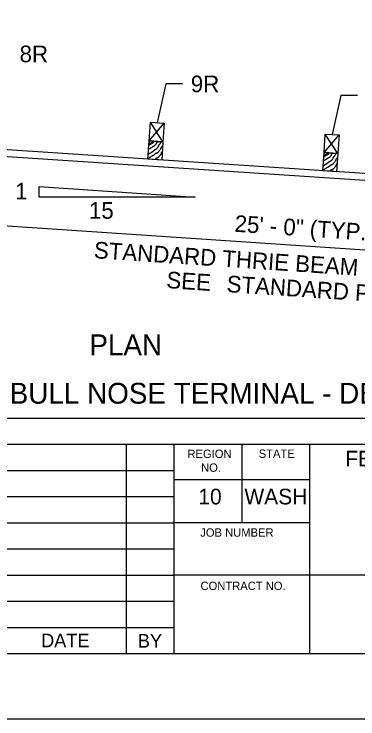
# Model space of a CAD drawing. Extents: x 1312564.2 to 1312581.5, y 1207298.4 to 1207352.6.
# Drawn here: x 1312570.095 to 1312571.742, y 1207298.421 to 1207301.791 of the extents above; entities that cross this region are included whole.
import ezdxf

# ---------------------------------------------------------------- set-up
doc = ezdxf.new("R2010")
doc.units = 0
for name, color, linetype in [('Level 1', 7, 'Continuous'), ('Level 13', 7, 'Continuous'), ('Level 14', 7, 'Continuous'), ('Level 15', 7, 'Continuous'), ('Level 2', 7, 'Continuous'), ('Level 20', 7, 'Continuous'), ('SH_GI_SheetTextInCells', 7, 'Continuous')]:
    doc.layers.add(name, color=color, linetype=linetype)

msp = doc.modelspace()

# ---------------------------------------------------------------- linework, layer by layer
at = {"layer": 'Level 1'}
for p, q in [((1312565.4154872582, 1207299.8593171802), (1312581.1654872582, 1207299.8593171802)), ((1312565.4154872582, 1207299.7342171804), (1312572.8721328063, 1207299.7342171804)), ((1312570.6319170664, 1207299.7342171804), (1312570.6319170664, 1207298.7334171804)), ((1312570.8605498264, 1207299.7342171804), (1312570.8605498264, 1207298.7334171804)), ((1312571.1873610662, 1207299.3589171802), (1312571.1873610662, 1207299.7342171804)), ((1312571.5110448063, 1207298.7334171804), (1312571.5110448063, 1207299.7342171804)), ((1312567.5976316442, 1207299.60911418), (1312570.8621007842, 1207299.60911418)), ((1312571.5112449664, 1207299.5644114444), (1312570.8621010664, 1207299.5644114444)), ((1312567.5976316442, 1207299.48401418), (1312570.8621007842, 1207299.48401418)), ((1312565.4154872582, 1207299.3589171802), (1312570.8621010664, 1207299.3589171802)), ((1312571.5112449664, 1207299.3589171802), (1312570.8621010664, 1207299.3589171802)), ((1312565.4154872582, 1207299.2338171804), (1312570.8621010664, 1207299.2338171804)), ((1312565.4154872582, 1207299.1087171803), (1312570.8621010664, 1207299.1087171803)), ((1312572.8721328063, 1207299.1087171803), (1312570.8621010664, 1207299.1087171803)), ((1312565.4154872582, 1207298.9836171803), (1312570.8621010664, 1207298.9836171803)), ((1312565.4154872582, 1207298.8585171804), (1312570.8621010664, 1207298.8585171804)), ((1312565.4154872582, 1207298.7334171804), (1312581.1654872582, 1207298.7334171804))]:
    msp.add_line(p, q, dxfattribs=at)
at = {"layer": 'Level 13'}
for points in [[(1312570.8071573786, 1207301.163427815), (1312570.8027456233, 1207301.1569541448), (1312570.802085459, 1207301.1562888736), (1312570.8012732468, 1207301.155764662), (1312570.8004554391, 1207301.1552460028), (1312570.7997784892, 1207301.1545973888), (1312570.7992182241, 1207301.1536536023), (1312570.7988187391, 1207301.152627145), (1312570.7983023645, 1207301.1504244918), (1312570.7978298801, 1207301.1481859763), (1312570.797264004, 1207301.1466017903), (1312570.7970017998, 1207301.1461081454), (1312570.793941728, 1207301.141220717), (1312570.7905743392, 1207301.1365573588), (1312570.7868166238, 1207301.1321866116), (1312570.784765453, 1207301.130132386), (1312570.7836922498, 1207301.1291418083), (1312570.7825855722, 1207301.1281770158), (1312570.7811749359, 1207301.12716844), (1312570.779645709, 1207301.1263642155), (1312570.776395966, 1207301.1251071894), (1312570.7731653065, 1207301.1238826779), (1312570.7709527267, 1207301.1226708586), (1312570.7702826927, 1207301.1221674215), (1312570.7695642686, 1207301.1214058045), (1312570.7689385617, 1207301.1205293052), (1312570.7682930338, 1207301.1196731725), (1312570.767515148, 1207301.1189726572), (1312570.763791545, 1207301.1166892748), (1312570.7599829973, 1207301.1145276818), (1312570.7561839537, 1207301.1123467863), (1312570.7524888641, 1207301.1100054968), (1312570.7368510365, 1207301.0993171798)], [(1312570.8003638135, 1207301.1814220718), (1312570.7972739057, 1207301.1764844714), (1312570.7954083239, 1207301.173580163), (1312570.793484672, 1207301.170712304), (1312570.7915210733, 1207301.167873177), (1312570.789535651, 1207301.1650550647), (1312570.7892304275, 1207301.1647300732), (1312570.7888550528, 1207301.1644801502), (1312570.7879852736, 1207301.1641077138), (1312570.7871091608, 1207301.163742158), (1312570.7864095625, 1207301.1631878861), (1312570.7860680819, 1207301.1626926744), (1312570.7857782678, 1207301.16216852), (1312570.7853252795, 1207301.161048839), (1312570.7847273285, 1207301.1586321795), (1312570.7841619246, 1207301.1561852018), (1312570.78348625, 1207301.1544788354), (1312570.7831752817, 1207301.1539552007), (1312570.7814320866, 1207301.1514727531), (1312570.7795401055, 1207301.1490977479), (1312570.777487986, 1207301.1468514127), (1312570.775264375, 1207301.144754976), (1312570.7741153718, 1207301.1439121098), (1312570.7728579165, 1207301.143232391), (1312570.7701697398, 1207301.1421474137), (1312570.767504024, 1207301.1410700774), (1312570.766274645, 1207301.1403999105), (1312570.7651649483, 1207301.139570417), (1312570.764742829, 1207301.1389820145), (1312570.7644500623, 1207301.138271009), (1312570.7641374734, 1207301.137580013), (1312570.763655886, 1207301.137051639), (1312570.7376506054, 1207301.1201799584)], [(1312570.783531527, 1207301.182544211), (1312570.7791813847, 1207301.1762695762), (1312570.7789475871, 1207301.1760503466), (1312570.7786440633, 1207301.175924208), (1312570.777919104, 1207301.1758288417), (1312570.7771890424, 1207301.175738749), (1312570.7766364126, 1207301.1754092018), (1312570.7764793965, 1207301.1751753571), (1312570.7763493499, 1207301.1749273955), (1312570.7761555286, 1207301.1743966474), (1312570.7759305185, 1207301.1732485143), (1312570.7757272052, 1207301.1720851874), (1312570.775560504, 1207301.1715354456), (1312570.77531141, 1207301.1710270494), (1312570.774418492, 1207301.1696106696), (1312570.7734979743, 1207301.1682062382), (1312570.771536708, 1207301.1654696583), (1312570.7681538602, 1207301.161682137), (1312570.7675235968, 1207301.1611025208), (1312570.7668712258, 1207301.1605406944), (1312570.765961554, 1207301.1599116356), (1312570.7649721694, 1207301.1594263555), (1312570.7628654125, 1207301.1587027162), (1312570.7607732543, 1207301.1580009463), (1312570.7593474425, 1207301.1572670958), (1312570.7591293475, 1207301.1571148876), (1312570.7589179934, 1207301.1569522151), (1312570.758344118, 1207301.1563314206), (1312570.7578531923, 1207301.1556066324), (1312570.757340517, 1207301.1549060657), (1312570.756701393, 1207301.1543579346), (1312570.7409179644, 1207301.145169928)], [(1312570.7667394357, 1207301.1836636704), (1312570.7651913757, 1207301.1814273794), (1312570.7648477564, 1207301.18091515), (1312570.7645125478, 1207301.18038888), (1312570.7625128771, 1207301.1771599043), (1312570.7609746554, 1207301.1752319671), (1312570.7590522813, 1207301.1737817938), (1312570.7526782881, 1207301.1704850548), (1312570.7420683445, 1207301.1649974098)], [(1312570.7587838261, 1207301.184194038), (1312570.7584000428, 1207301.1824398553), (1312570.757974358, 1207301.1807241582), (1312570.7573869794, 1207301.1791569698), (1312570.7569952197, 1207301.1784634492), (1312570.7567682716, 1207301.1781452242), (1312570.7566462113, 1207301.1779939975), (1312570.7565829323, 1207301.1779204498), (1312570.756550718, 1207301.177884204), (1312570.7565344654, 1207301.177866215), (1312570.756518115, 1207301.177848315), (1312570.7562144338, 1207301.1775351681), (1312570.755893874, 1207301.1772375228), (1312570.7552054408, 1207301.1766856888), (1312570.7536625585, 1207301.1757344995), (1312570.7500986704, 1207301.174271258), (1312570.7462514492, 1207301.173068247), (1312570.7443544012, 1207301.1724423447), (1312570.7425458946, 1207301.171735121)], [(1312570.8052260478, 1207301.1344575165), (1312570.8045071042, 1207301.1334083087), (1312570.804205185, 1207301.1330493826), (1312570.8038470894, 1207301.1327426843), (1312570.803035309, 1207301.1322182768), (1312570.802217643, 1207301.1316996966), (1312570.8018521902, 1207301.1314002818), (1312570.8015399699, 1207301.1310515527), (1312570.8009784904, 1207301.130108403), (1312570.8005784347, 1207301.1290822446), (1312570.800062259, 1207301.1268794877), (1312570.7995907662, 1207301.1246404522), (1312570.799246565, 1207301.1235689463), (1312570.7987632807, 1207301.1225623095), (1312570.7980218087, 1207301.1213237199), (1312570.7972637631, 1207301.1200968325), (1312570.7923110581, 1207301.113029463), (1312570.7885502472, 1207301.1086609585), (1312570.7865079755, 1207301.1066002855), (1312570.7854428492, 1207301.1056038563), (1312570.7843470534, 1207301.1046311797), (1312570.7829254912, 1207301.1036415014), (1312570.781347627, 1207301.1028991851), (1312570.7779691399, 1207301.1017981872), (1312570.7747038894, 1207301.1006112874), (1312570.773267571, 1207301.099761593), (1312570.772044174, 1207301.0986215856), (1312570.770850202, 1207301.0971178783)], [(1312571.6443803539, 1207301.1076136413), (1312571.6399685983, 1207301.1011399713), (1312571.6393084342, 1207301.1004746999), (1312571.638496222, 1207301.0999504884), (1312571.6376784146, 1207301.0994318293), (1312571.6370014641, 1207301.098783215), (1312571.636441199, 1207301.0978394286), (1312571.636041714, 1207301.0968129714), (1312571.6355253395, 1207301.094610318), (1312571.6350528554, 1207301.0923718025), (1312571.634486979, 1207301.0907876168), (1312571.6342247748, 1207301.0902939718), (1312571.631164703, 1207301.0854065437), (1312571.6277973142, 1207301.0807431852), (1312571.6240395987, 1207301.0763724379), (1312571.621988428, 1207301.0743182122), (1312571.620915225, 1207301.0733276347), (1312571.6198085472, 1207301.072362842), (1312571.6183979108, 1207301.0713542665), (1312571.616868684, 1207301.070550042), (1312571.613618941, 1207301.0692930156), (1312571.6103882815, 1207301.0680685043), (1312571.6081757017, 1207301.066856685), (1312571.6075056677, 1207301.0663532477), (1312571.606787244, 1207301.0655916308), (1312571.6061615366, 1207301.0647151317), (1312571.6055160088, 1207301.0638589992), (1312571.6047381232, 1207301.0631584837), (1312571.60101452, 1207301.0608751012), (1312571.5972059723, 1207301.058713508), (1312571.5934069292, 1207301.0565326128), (1312571.589711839, 1207301.0541913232), (1312571.5740740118, 1207301.0435030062)], [(1312571.6375867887, 1207301.1256078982), (1312571.6344968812, 1207301.1206702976), (1312571.6326312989, 1207301.1177659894), (1312571.630707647, 1207301.1148981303), (1312571.6287440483, 1207301.1120590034), (1312571.626758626, 1207301.1092408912), (1312571.6264534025, 1207301.1089158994), (1312571.6260780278, 1207301.108665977), (1312571.6252082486, 1207301.1082935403), (1312571.624332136, 1207301.1079279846), (1312571.6236325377, 1207301.1073737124), (1312571.6232910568, 1207301.106878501), (1312571.623001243, 1207301.1063543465), (1312571.6225482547, 1207301.1052346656), (1312571.6219503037, 1207301.1028180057), (1312571.6213848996, 1207301.1003710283), (1312571.620709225, 1207301.0986646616), (1312571.6203982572, 1207301.098141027), (1312571.6186550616, 1207301.0956585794), (1312571.6167630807, 1207301.093283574), (1312571.614710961, 1207301.0910372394), (1312571.61248735, 1207301.0889408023), (1312571.6113383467, 1207301.088097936), (1312571.6100808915, 1207301.0874182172), (1312571.6073927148, 1207301.08633324), (1312571.6047269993, 1207301.0852559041), (1312571.60349762, 1207301.084585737), (1312571.6023879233, 1207301.0837562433), (1312571.601965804, 1207301.083167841), (1312571.6016730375, 1207301.0824568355), (1312571.6013604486, 1207301.0817658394), (1312571.6008788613, 1207301.0812374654), (1312571.5748735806, 1207301.0643657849)], [(1312571.620754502, 1207301.1267300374), (1312571.6164043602, 1207301.1204554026), (1312571.6161705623, 1207301.1202361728), (1312571.6158670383, 1207301.1201100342), (1312571.6151420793, 1207301.1200146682), (1312571.6144120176, 1207301.1199245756), (1312571.6138593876, 1207301.119595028), (1312571.6137023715, 1207301.1193611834), (1312571.6135723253, 1207301.119113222), (1312571.6133785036, 1207301.1185824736), (1312571.6131534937, 1207301.1174343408), (1312571.6129501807, 1207301.1162710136), (1312571.6127834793, 1207301.115721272), (1312571.6125343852, 1207301.1152128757), (1312571.6116414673, 1207301.113796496), (1312571.6107209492, 1207301.1123920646), (1312571.6087596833, 1207301.1096554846), (1312571.605376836, 1207301.1058679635), (1312571.6047465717, 1207301.105288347), (1312571.6040942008, 1207301.1047265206), (1312571.6031845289, 1207301.104097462), (1312571.6021951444, 1207301.103612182), (1312571.6000883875, 1207301.102888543), (1312571.5979962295, 1207301.1021867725), (1312571.5965704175, 1207301.1014529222), (1312571.5963523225, 1207301.1013007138), (1312571.5961409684, 1207301.1011380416), (1312571.5955670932, 1207301.1005172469), (1312571.5950761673, 1207301.0997924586), (1312571.5945634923, 1207301.099091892), (1312571.593924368, 1207301.098543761), (1312571.5781409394, 1207301.0893557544)], [(1312571.6039624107, 1207301.1278494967), (1312571.6024143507, 1207301.125613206), (1312571.6020707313, 1207301.1251009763), (1312571.6017355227, 1207301.1245747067), (1312571.599735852, 1207301.1213457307), (1312571.5981976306, 1207301.1194177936), (1312571.5962752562, 1207301.11796762), (1312571.5899012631, 1207301.1146708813), (1312571.5792913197, 1207301.1091832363)], [(1312571.5960068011, 1207301.1283798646), (1312571.5956230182, 1207301.1266256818), (1312571.595197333, 1207301.1249099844), (1312571.5946099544, 1207301.1233427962), (1312571.5942181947, 1207301.122649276), (1312571.5939912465, 1207301.1223310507), (1312571.5938691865, 1207301.1221798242), (1312571.5938059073, 1207301.1221062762), (1312571.593773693, 1207301.1220700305), (1312571.5937574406, 1207301.122052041), (1312571.5937410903, 1207301.1220341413), (1312571.593437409, 1207301.1217209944), (1312571.5931168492, 1207301.121423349), (1312571.5924284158, 1207301.1208715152), (1312571.5908855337, 1207301.119920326), (1312571.5873216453, 1207301.1184570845), (1312571.5834744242, 1207301.1172540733), (1312571.5815773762, 1207301.1166281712), (1312571.5797688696, 1207301.1159209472)], [(1312571.642449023, 1207301.0786433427), (1312571.6417300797, 1207301.0775941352), (1312571.64142816, 1207301.0772352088), (1312571.6410700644, 1207301.0769285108), (1312571.640258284, 1207301.0764041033), (1312571.6394406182, 1207301.0758855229), (1312571.6390751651, 1207301.0755861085), (1312571.638762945, 1207301.0752373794), (1312571.6382014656, 1207301.0742942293), (1312571.6378014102, 1207301.073268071), (1312571.6372852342, 1207301.0710653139), (1312571.6368137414, 1207301.0688262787), (1312571.63646954, 1207301.0677547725), (1312571.6359862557, 1207301.0667481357), (1312571.6352447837, 1207301.065509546), (1312571.6344867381, 1207301.0642826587), (1312571.6295340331, 1207301.0572152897), (1312571.6257732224, 1207301.052846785), (1312571.6237309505, 1207301.0507861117), (1312571.6226658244, 1207301.0497896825), (1312571.6215700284, 1207301.0488170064), (1312571.6201484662, 1207301.0478273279), (1312571.618570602, 1207301.0470850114), (1312571.6151921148, 1207301.0459840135), (1312571.6119268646, 1207301.0447971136), (1312571.6104905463, 1207301.0439474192), (1312571.609267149, 1207301.042807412), (1312571.608073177, 1207301.0413037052)]]:
    msp.add_spline(points, degree=3, dxfattribs=at)
at = {"layer": 'Level 14'}
for p, q in [((1312570.7421442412, 1207301.1853033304), (1312570.8142069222, 1207301.269172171)), ((1312570.8083216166, 1207301.1808915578), (1312570.748029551, 1207301.273583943)), ((1312571.5793672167, 1207301.1294891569), (1312571.6514298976, 1207301.2133579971)), ((1312571.6455445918, 1207301.1250773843), (1312571.5852525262, 1207301.2177697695))]:
    msp.add_line(p, q, dxfattribs=at)
at = {"layer": 'Level 15'}
for p, q in [((1312570.821919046, 1207301.4573174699), (1312570.7811182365, 1207301.2713780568)), ((1312570.9016476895, 1207301.4573174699), (1312570.821919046, 1207301.4573174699)), ((1312571.6591420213, 1207301.401503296), (1312571.6183412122, 1207301.2155638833)), ((1312571.7388706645, 1207301.401503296), (1312571.6591420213, 1207301.401503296)), ((1312568.209466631, 1207301.2673344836), (1312575.5205605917, 1207300.7799342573)), ((1312568.207260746, 1207301.234245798), (1312575.5205605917, 1207300.7466985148)), ((1312570.2153975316, 1207300.9162212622), (1312570.2153975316, 1207300.9660516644)), ((1312570.2153975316, 1207300.9660516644), (1312570.9628535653, 1207300.9162212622)), ((1312570.9628535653, 1207300.9162212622), (1312570.2153975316, 1207300.9162212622)), ((1312569.9194786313, 1207300.7877419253), (1312573.229335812, 1207300.5670875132))]:
    msp.add_line(p, q, dxfattribs=at)
for points in [[(1312570.8083216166, 1207301.1808915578), (1312570.7421442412, 1207301.1853033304), (1312570.748029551, 1207301.273583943), (1312570.8142069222, 1207301.269172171)], [(1312571.6455445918, 1207301.1250773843), (1312571.5793672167, 1207301.1294891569), (1312571.5852525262, 1207301.2177697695), (1312571.6514298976, 1207301.2133579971)], [(1312570.8024363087, 1207301.0926109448), (1312570.7362589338, 1207301.0970227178), (1312570.7421442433, 1207301.1853033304), (1312570.8083216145, 1207301.180891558)], [(1312571.6396592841, 1207301.0367967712), (1312571.5734819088, 1207301.041208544), (1312571.5793672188, 1207301.1294891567), (1312571.6455445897, 1207301.1250773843)]]:
    msp.add_lwpolyline(points, close=True, dxfattribs=at)
at = {"layer": 'Level 2'}
msp.add_lwpolyline([(1312564.4779872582, 1207298.4209171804), (1312581.4779872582, 1207298.4209171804), (1312581.4779872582, 1207309.4209171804), (1312564.4779872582, 1207309.4209171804)], close=True, dxfattribs=at)

# ---------------------------------------------------------------- texts
at = {"layer": 'Level 20'}
for s, height, p in [('8R', 0.07972865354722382, (1312570.1219565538, 1207301.5607624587)), ('9R', 0.07972865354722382, (1312570.9415120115, 1207301.417453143)), ('1', 0.07972865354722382, (1312570.100703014, 1207300.9046222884)), ('15', 0.07972865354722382, (1312570.4539357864, 1207300.812416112)), ('PLAN', 0.09966079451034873, (1312570.455915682, 1207300.1596369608)), ('BEAM GUARDRAIL BULL NOSE TERMINAL - DESIGN 2', 0.0996608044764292, (1312568.845170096, 1207299.9282150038))]:
    msp.add_text(s, height=height, dxfattribs=at).set_placement(p)
for s, p in [('25\' - 0" (TYP.)', (1312571.149119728, 1207300.7505815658)), ('STANDARD THRIE BEAM RAIL ELEMENTS', (1312570.47573092, 1207300.62409583)), ('SEE ', (1312570.8226924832, 1207300.4811941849)), ('STANDARD PLAN C-1a', (1312571.1109569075, 1207300.4620476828))]:
    msp.add_text(s, height=0.07972865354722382, rotation=356.20000000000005, dxfattribs=at).set_placement(p)
at = {"layer": 'SH_GI_SheetTextInCells'}
for s, height, p in [('REGION', 0.04003199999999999, (1312570.9253455, 1207299.6685947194)), ('STATE', 0.04003199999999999, (1312571.2665428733, 1207299.6690901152)), ('FED.AID PROJ.NO.', 0.07505999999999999, (1312571.6807192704, 1207299.6279172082)), ('NO.', 0.04003199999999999, (1312570.9906725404, 1207299.6024318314)), ('10', 0.07505999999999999, (1312570.977576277, 1207299.4464971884)), ('WASH', 0.07505999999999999, (1312571.1980781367, 1207299.4464971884)), ('JOB NUMBER', 0.04003199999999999, (1312570.9866901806, 1207299.2921588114)), ('CONTRACT NO.', 0.04003199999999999, (1312570.9879956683, 1207299.0371249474)), ('DATE', 0.06505199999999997, (1312570.2246138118, 1207298.7634511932)), ('BY', 0.06505199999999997, (1312570.6879542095, 1207298.7618749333))]:
    msp.add_text(s, height=height, dxfattribs=at).set_placement(p)

doc.saveas('drawing.dxf')
